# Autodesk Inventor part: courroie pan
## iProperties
Created: 2011-01
Part Number: courroie pan
Document SubType Name: Modeling
Designer: eric
Density: 1 g/cm^3
Mass: 1.41186 g
Surface Area: 42.1621 cm^2
Volume: 1.41186 cm^3
Author: eric
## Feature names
1. Base1
